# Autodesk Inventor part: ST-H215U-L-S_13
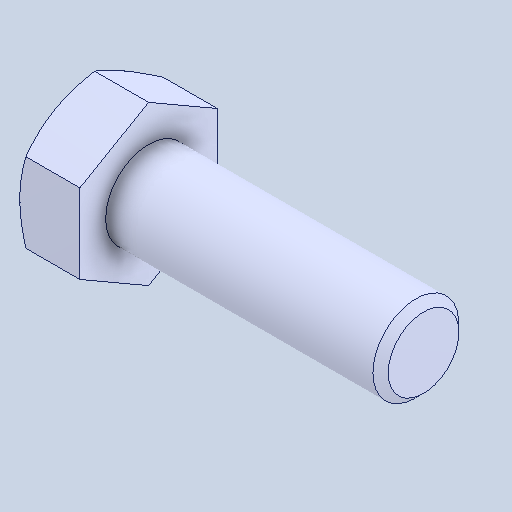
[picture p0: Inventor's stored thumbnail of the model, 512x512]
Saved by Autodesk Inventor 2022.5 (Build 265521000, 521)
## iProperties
Created: 2024-07
Part Number: ST-H215U-L-S_13
Material: 一般
Document SubType Name: Modeling
Designer: ImaoCorp
Density: 1 g/cm^3
Appearance: 既定
Author: ImaoCorp
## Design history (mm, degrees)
feature "ST-H215U-L-S_13"
node "ソリッド1"
